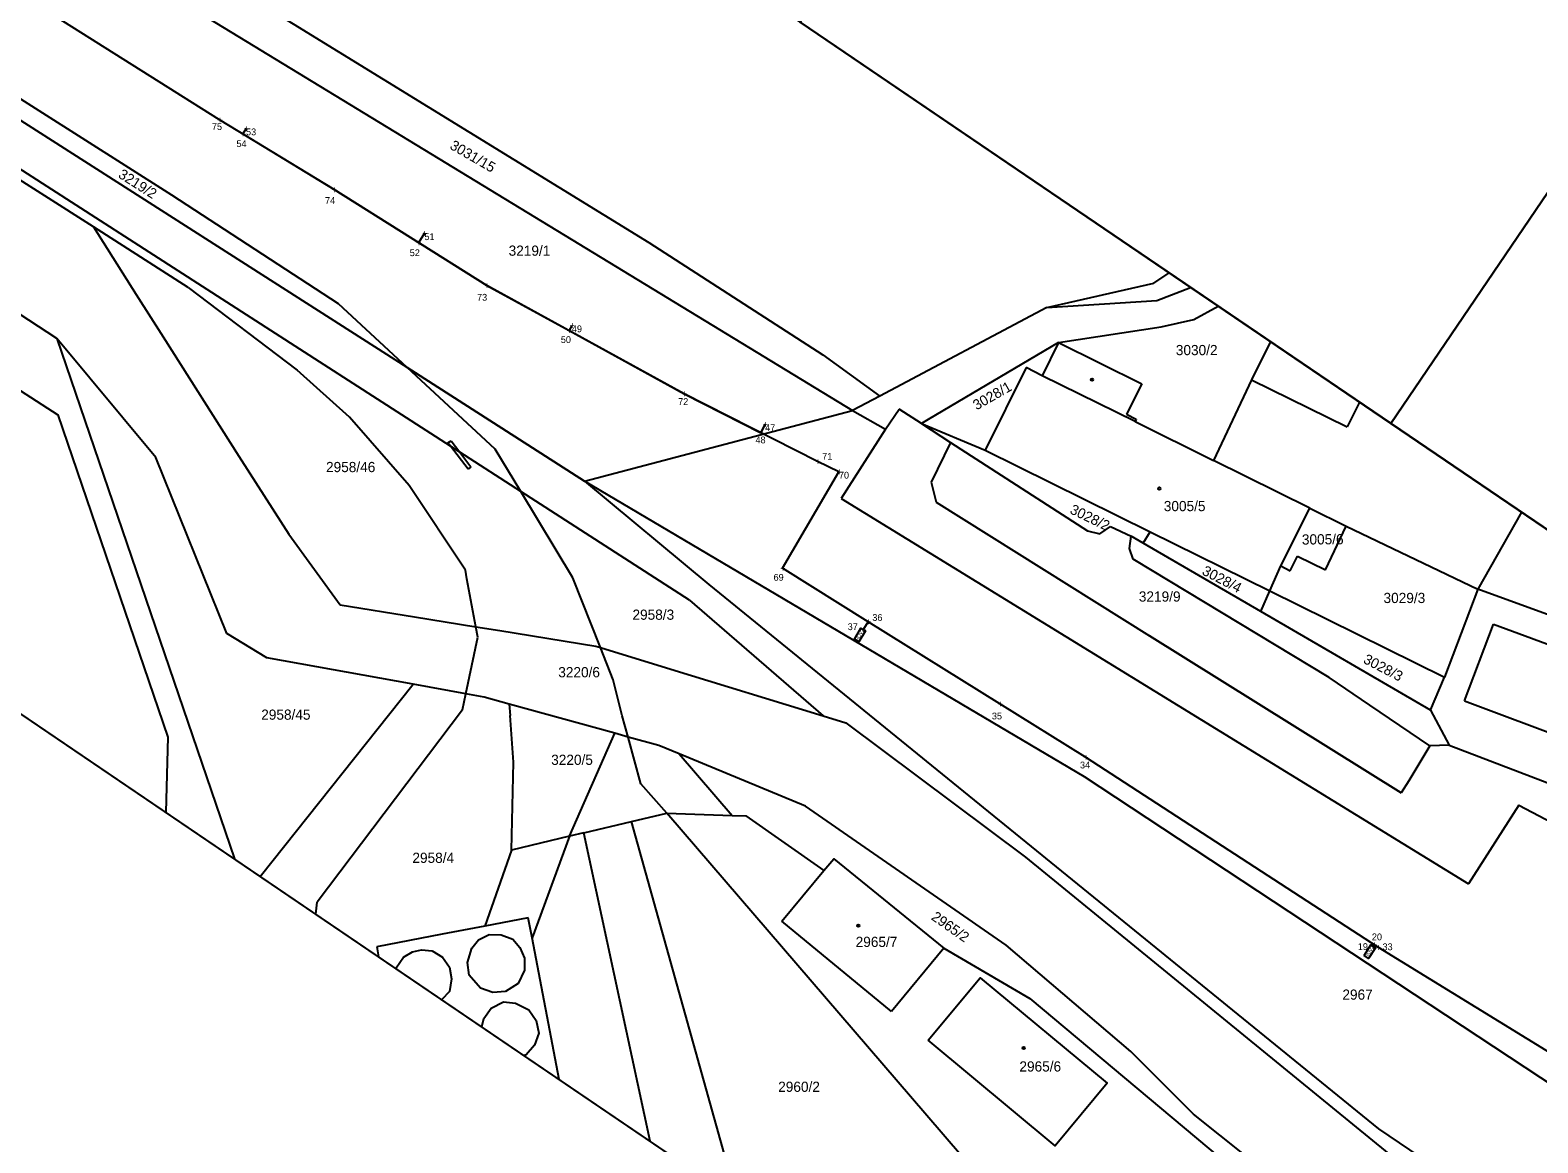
# Model space of a CAD drawing. Extents: x -621058 to -620023, y -1122866 to -1122030.
# Drawn here: x -620566.7 to -620345, y -1122671.6 to -1122508 of the extents above; entities that cross this region are included whole.
import ezdxf

# ---------------------------------------------------------------- set-up
doc = ezdxf.new("R2010")
doc.units = 0
for name, color, linetype in [('060604_ROZVODY_SEE', 7, 'Continuous'), ('BODY', 7, 'Continuous'), ('BODY POPIS', 7, 'Continuous'), ('RÁMY', 7, 'Continuous'), ('UZEMNĚNÍ', 7, 'Continuous'), ('Vrstva 53', 7, 'Continuous'), ('Vrstva 55', 7, 'Continuous'), ('Vrstva 56', 7, 'Continuous'), ('Vrstva 57', 7, 'Continuous')]:
    doc.layers.add(name, color=color, linetype=linetype)

msp = doc.modelspace()

# ---------------------------------------------------------------- linework, layer by layer
at = {"layer": '060604_ROZVODY_SEE'}
for p, q in [((-620535, -1122522.48), (-620535.49, -1122523.28)), ((-620508.77, -1122537.89), (-620509.64, -1122539.27)), ((-620487.09, -1122551.44), (-620487.51, -1122552.2)), ((-620458.67, -1122565.97), (-620459.3, -1122567.21)), ((-620369.27, -1122642.75), (-620369.11, -1122642.5))]:
    msp.add_line(p, q, dxfattribs=at)
for points in [[(-620443.53, -1122595), (-620456.11, -1122587.12), (-620447.82, -1122572.96), (-620450.95, -1122571.45), (-620470.59, -1122561.48), (-620499.61, -1122545.57), (-620522.04, -1122531.47), (-620538.89, -1122521.21), (-620599.21, -1122483.22), (-620683.52, -1122429.44), (-620756.33, -1122383.52), (-620765.8, -1122398.39)], [(-620243.03, -1122716), (-620248.32, -1122722.77), (-620259.89, -1122713.57), (-620277.71, -1122700.9), (-620282.35, -1122705.3), (-620297.82, -1122689.49), (-620304.22, -1122684.86), (-620310.82, -1122680.06), (-620316.82, -1122675.99), (-620322.23, -1122672.32), (-620326.63, -1122669.41), (-620343.18, -1122658.46), (-620368.5, -1122642.9), (-620411.56, -1122614.92), (-620424.16, -1122607.09), (-620443.53, -1122595), (-620444.24, -1122596.15)]]:
    msp.add_lwpolyline(points, dxfattribs=at)
for points in [[(-620445.54, -1122597.56), (-620444.58, -1122595.95), (-620443.91, -1122596.35), (-620444.87, -1122597.96)], [(-620370.61, -1122644.11), (-620369.6, -1122642.54), (-620368.94, -1122642.96), (-620369.95, -1122644.54)]]:
    msp.add_lwpolyline(points, close=True, dxfattribs=at)
at = {"layer": 'RÁMY'}
for points in [[(-620974.7, -1122152.91), (-620106.07, -1122742.82), (-620189.51, -1122865.67), (-621058.13, -1122275.76)], [(-620887.83, -1122211.9), (-620106.07, -1122742.82), (-620189.51, -1122865.67), (-620971.26, -1122334.75)], [(-620370.09, -1122384.01), (-620283.23, -1122443), (-620366.66, -1122565.85), (-620453.52, -1122506.86)], [(-620283.23, -1122443), (-620196.37, -1122501.99), (-620279.8, -1122624.84), (-620366.66, -1122565.85)]]:
    msp.add_lwpolyline(points, close=True, dxfattribs=at)
at = {"layer": 'UZEMNĚNÍ'}
msp.add_lwpolyline([(-620535, -1122522.48), (-620535.49, -1122523.28), (-620522.04, -1122531.47), (-620499.61, -1122545.57), (-620487.51, -1122552.2), (-620470.59, -1122561.48), (-620459.3, -1122567.21), (-620458.67, -1122565.97)], dxfattribs=at)
at = {"layer": 'Vrstva 53'}
for p, q in [((-620545.92, -1122532.26), (-620679.51, -1122447.56)), ((-620552.09, -1122499.2), (-620445.8, -1122563.95)), ((-620521.41, -1122548.27), (-620545.92, -1122532.26)), ((-620511.29, -1122557.64), (-620521.41, -1122548.27)), ((-620485.21, -1122574.33), (-620511.29, -1122557.64)), ((-620445.8, -1122563.95), (-620440.98, -1122566.69)), ((-620440.98, -1122566.69), (-620438.97, -1122563.76)), ((-620435.69, -1122565.88), (-620438.97, -1122563.76)), ((-620440.98, -1122566.69), (-620447.48, -1122576.88)), ((-620435.69, -1122565.88), (-620431.39, -1122568.66)), ((-620431.39, -1122568.66), (-620434.26, -1122574.5)), ((-620411.71, -1122617.81), (-620485.21, -1122574.33)), ((-620434.26, -1122574.5), (-620433.53, -1122577.42)), ((-620447.48, -1122576.88), (-620355.23, -1122633.54)), ((-620433.53, -1122577.42), (-620402.13, -1122597.06)), ((-620402.13, -1122597.06), (-620365.14, -1122620.19)), ((-620358.11, -1122613.18), (-620360.91, -1122613.28)), ((-620358.11, -1122613.18), (-620335.54, -1122621.75)), ((-620361.94, -1122614.97), (-620364.03, -1122618.38)), ((-620334.71, -1122668.63), (-620411.71, -1122617.81)), ((-620364.03, -1122618.38), (-620365.14, -1122620.19)), ((-620347.83, -1122621.96), (-620355.23, -1122633.54)), ((-620347.83, -1122621.96), (-620296.23, -1122649.3))]:
    msp.add_line(p, q, dxfattribs=at)
at = {"layer": 'Vrstva 55'}
for p, q in [((-620545.92, -1122532.26), (-620679.51, -1122447.56)), ((-620557.45, -1122536.96), (-620684.91, -1122455.63)), ((-620548.9, -1122494.24), (-620475.79, -1122539.24)), ((-620552.09, -1122499.2), (-620445.8, -1122563.95)), ((-620511.29, -1122557.64), (-620587.17, -1122509.18)), ((-620521.41, -1122548.27), (-620545.92, -1122532.26)), ((-620557.45, -1122536.96), (-620551.15, -1122546.87)), ((-620543.5, -1122545.86), (-620557.45, -1122536.96)), ((-620475.79, -1122539.24), (-620450.17, -1122555.76)), ((-620417.25, -1122548.82), (-620401.53, -1122545.24)), ((-620401.53, -1122545.24), (-620399.25, -1122543.72)), ((-620551.15, -1122546.87), (-620547.19, -1122553.1)), ((-620543.5, -1122545.86), (-620527.5, -1122558.02)), ((-620511.29, -1122557.64), (-620521.41, -1122548.27)), ((-620417.25, -1122548.82), (-620441.78, -1122561.82)), ((-620548.28, -1122570.88), (-620562.8, -1122553.35)), ((-620562.8, -1122553.35), (-620536.71, -1122629.87)), ((-620547.19, -1122553.1), (-620536.04, -1122570.64)), ((-620415.52, -1122553.94), (-620434.68, -1122565.28)), ((-620415.52, -1122553.94), (-620417.91, -1122558.83)), ((-620415.52, -1122553.94), (-620403.26, -1122560.03)), ((-620384.37, -1122553.82), (-620387.17, -1122559.43)), ((-620450.17, -1122555.76), (-620441.78, -1122561.82)), ((-620519.77, -1122564.93), (-620527.5, -1122558.02)), ((-620498.35, -1122569.65), (-620511.29, -1122557.64)), ((-620511.29, -1122557.64), (-620485.21, -1122574.33)), ((-620420.27, -1122557.63), (-620426.32, -1122569.77)), ((-620417.91, -1122558.83), (-620420.27, -1122557.63)), ((-620403.26, -1122560.03), (-620405.52, -1122564.49)), ((-620387.17, -1122559.43), (-620392.72, -1122571.3)), ((-620387.17, -1122559.43), (-620373.07, -1122566.34)), ((-620441.78, -1122561.82), (-620445.8, -1122563.95)), ((-620371.29, -1122562.71), (-620373.07, -1122566.34)), ((-620511.02, -1122574.99), (-620519.77, -1122564.93)), ((-620445.8, -1122563.95), (-620440.98, -1122566.69)), ((-620440.98, -1122566.69), (-620438.97, -1122563.76)), ((-620435.69, -1122565.88), (-620438.97, -1122563.76)), ((-620434.68, -1122565.28), (-620435.69, -1122565.88)), ((-620405.52, -1122564.49), (-620404.12, -1122565.22)), ((-620404.12, -1122565.22), (-620404.28, -1122565.56)), ((-620440.98, -1122566.69), (-620447.48, -1122576.88)), ((-620435.69, -1122565.88), (-620426.32, -1122569.77)), ((-620435.69, -1122565.88), (-620431.39, -1122568.66)), ((-620404.28, -1122565.56), (-620392.72, -1122571.3)), ((-620494.61, -1122575.85), (-620498.35, -1122569.65)), ((-620431.39, -1122568.66), (-620434.26, -1122574.5)), ((-620431.39, -1122568.66), (-620411.27, -1122581.65)), ((-620426.32, -1122569.77), (-620402.04, -1122581.77)), ((-620537.83, -1122596.73), (-620548.28, -1122570.88)), ((-620536.04, -1122570.64), (-620528.72, -1122582.15)), ((-620378.57, -1122578.31), (-620392.72, -1122571.3)), ((-620502.74, -1122587.44), (-620511.02, -1122574.99)), ((-620486.95, -1122588.56), (-620494.61, -1122575.85)), ((-620469.8, -1122591.86), (-620494.61, -1122575.85)), ((-620485.21, -1122574.33), (-620466.94, -1122589.51)), ((-620411.71, -1122617.81), (-620485.21, -1122574.33)), ((-620434.26, -1122574.5), (-620433.53, -1122577.42)), ((-620447.48, -1122576.88), (-620355.23, -1122633.54)), ((-620433.53, -1122577.42), (-620402.13, -1122597.06)), ((-620382.82, -1122586.79), (-620378.57, -1122578.31)), ((-620378.57, -1122578.31), (-620373.23, -1122580.96)), ((-620347.47, -1122578.88), (-620353.86, -1122590.22)), ((-620528.72, -1122582.15), (-620521.17, -1122592.53)), ((-620411.27, -1122581.65), (-620409.46, -1122582.07)), ((-620409.46, -1122582.07), (-620407.91, -1122580.98)), ((-620407.91, -1122580.98), (-620404.87, -1122582.42)), ((-620403.1, -1122583.45), (-620404.87, -1122582.42)), ((-620403.1, -1122583.45), (-620402.04, -1122581.77)), ((-620402.04, -1122581.77), (-620384.45, -1122590.46)), ((-620376.29, -1122587.36), (-620373.23, -1122580.96)), ((-620373.23, -1122580.96), (-620353.86, -1122590.22)), ((-620385.78, -1122593.52), (-620403.1, -1122583.45)), ((-620502.51, -1122588.68), (-620502.74, -1122587.44)), ((-620384.45, -1122590.46), (-620382.82, -1122586.79)), ((-620382.82, -1122586.79), (-620381.45, -1122587.52)), ((-620381.45, -1122587.52), (-620380.38, -1122585.36)), ((-620380.38, -1122585.36), (-620376.29, -1122587.36)), ((-620501.2, -1122595.75), (-620502.51, -1122588.68)), ((-620482.88, -1122598.82), (-620486.95, -1122588.56)), ((-620466.94, -1122589.51), (-620368.46, -1122669.58)), ((-620469.8, -1122591.86), (-620450.13, -1122608.86)), ((-620385.78, -1122593.52), (-620384.45, -1122590.46)), ((-620384.45, -1122590.46), (-620358.78, -1122603.15)), ((-620353.86, -1122590.22), (-620358.78, -1122603.15)), ((-620329.18, -1122599.21), (-620353.86, -1122590.22)), ((-620521.17, -1122592.53), (-620510.22, -1122594.3)), ((-620360.83, -1122608.03), (-620385.78, -1122593.52)), ((-620510.22, -1122594.3), (-620501.2, -1122595.75)), ((-620501.2, -1122595.75), (-620497.68, -1122596.32)), ((-620500.92, -1122597.26), (-620501.2, -1122595.75)), ((-620497.68, -1122596.32), (-620483.58, -1122598.6)), ((-620355.84, -1122606.66), (-620351.59, -1122595.35)), ((-620351.59, -1122595.35), (-620331.64, -1122602.77)), ((-620531.96, -1122600.32), (-620537.83, -1122596.73)), ((-620502.69, -1122605.61), (-620500.92, -1122597.26)), ((-620365.14, -1122620.19), (-620402.13, -1122597.06)), ((-620510.44, -1122604.21), (-620531.96, -1122600.32)), ((-620483.58, -1122598.6), (-620482.88, -1122598.82)), ((-620482.88, -1122598.82), (-620472.56, -1122601.98)), ((-620481, -1122603.54), (-620482.88, -1122598.82)), ((-620472.56, -1122601.98), (-620450.13, -1122608.86)), ((-620532.9, -1122632.46), (-620510.44, -1122604.21)), ((-620502.69, -1122605.61), (-620510.44, -1122604.21)), ((-620479.67, -1122608.86), (-620481, -1122603.54)), ((-620360.83, -1122608.03), (-620358.78, -1122603.15)), ((-620503.19, -1122607.95), (-620502.69, -1122605.61)), ((-620500, -1122606.09), (-620502.69, -1122605.61)), ((-620496.31, -1122607.11), (-620500, -1122606.09)), ((-620496.31, -1122607.11), (-620496.18, -1122608.79)), ((-620480.79, -1122611.41), (-620496.31, -1122607.11)), ((-620355.84, -1122606.66), (-620335.8, -1122614.14)), ((-620503.19, -1122607.95), (-620524.52, -1122636.25)), ((-620495.65, -1122615.65), (-620496.18, -1122608.79)), ((-620478.83, -1122611.96), (-620479.67, -1122608.86)), ((-620450.13, -1122608.86), (-620446.79, -1122609.88)), ((-620360.83, -1122608.03), (-620358.11, -1122613.18)), ((-620478.83, -1122611.96), (-620480.79, -1122611.41)), ((-620446.79, -1122609.88), (-620420.38, -1122629.64)), ((-620474.31, -1122613.21), (-620478.83, -1122611.96)), ((-620476.96, -1122618.82), (-620478.83, -1122611.96)), ((-620471.33, -1122614.44), (-620474.31, -1122613.21)), ((-620360.91, -1122613.28), (-620361.94, -1122614.97)), ((-620358.11, -1122613.18), (-620360.91, -1122613.28)), ((-620358.11, -1122613.18), (-620335.54, -1122621.75)), ((-620495.96, -1122628.58), (-620495.65, -1122615.65)), ((-620452.73, -1122622.13), (-620471.33, -1122614.44)), ((-620361.94, -1122614.97), (-620364.03, -1122618.38)), ((-620334.71, -1122668.63), (-620411.71, -1122617.81)), ((-620364.03, -1122618.38), (-620365.14, -1122620.19)), ((-620473.14, -1122623.15), (-620476.96, -1122618.82)), ((-620423.22, -1122642.55), (-620452.73, -1122622.13)), ((-620347.83, -1122621.96), (-620355.23, -1122633.54)), ((-620347.83, -1122621.96), (-620296.23, -1122649.3)), ((-620485.31, -1122626.04), (-620478.32, -1122624.38)), ((-620478.32, -1122624.38), (-620473.14, -1122623.15)), ((-620463.28, -1122678.3), (-620478.32, -1122624.38)), ((-620434.88, -1122667.63), (-620473.14, -1122623.15)), ((-620473.14, -1122623.15), (-620463.51, -1122623.5)), ((-620487.46, -1122626.56), (-620495.96, -1122628.58)), ((-620485.31, -1122626.04), (-620487.46, -1122626.56)), ((-620475.57, -1122671.39), (-620485.31, -1122626.04)), ((-620456.23, -1122639.05), (-620450.04, -1122631.61)), ((-620420.38, -1122629.64), (-620366.98, -1122673.23)), ((-620524.73, -1122638.01), (-620524.52, -1122636.25)), ((-620499.9, -1122639.77), (-620506.17, -1122640.97)), ((-620493.5, -1122638.55), (-620499.9, -1122639.77)), ((-620492.94, -1122641.47), (-620493.5, -1122638.55)), ((-620440.08, -1122652.3), (-620456.23, -1122639.05)), ((-620506.17, -1122640.97), (-620515.78, -1122642.8)), ((-620515.78, -1122642.8), (-620515.5, -1122644.28)), ((-620488.95, -1122662.31), (-620492.94, -1122641.47)), ((-620404.9, -1122658.18), (-620423.22, -1122642.55)), ((-620432.38, -1122643.03), (-620440.08, -1122652.3)), ((-620395.68, -1122667.41), (-620404.9, -1122658.18)), ((-620391.77, -1122717.74), (-620434.88, -1122667.63)), ((-620365.35, -1122691.52), (-620395.68, -1122667.41)), ((-620368.46, -1122669.58), (-620310.57, -1122708.76))]:
    msp.add_line(p, q, dxfattribs=at)
for points in [[(-620562.8, -1122553.35), (-620572.54, -1122547.06), (-620576.58, -1122544.45)], [(-620581.67, -1122552.32), (-620562.67, -1122564.59), (-620546.5, -1122612), (-620546.78, -1122623.03)], [(-620463.51, -1122623.5), (-620461.53, -1122623.57), (-620450.04, -1122631.61)], [(-620450.04, -1122631.61), (-620448.58, -1122629.86), (-620432.38, -1122643.03)], [(-620432.38, -1122643.03), (-620419.73, -1122650.41), (-620372.55, -1122689.97), (-620363.06, -1122698.75), (-620352.08, -1122712.18), (-620349.5, -1122720.4)], [(-620434.7, -1122656.53), (-620427.07, -1122647.39), (-620408.37, -1122662.86), (-620416.01, -1122672.06), (-620434.7, -1122656.53)]]:
    msp.add_lwpolyline(points, dxfattribs=at)
at = {"layer": 'Vrstva 56'}
for p, q in [((-620504.94, -1122569.2), (-620570.69, -1122526.84)), ((-620401.09, -1122547.76), (-620396.12, -1122545.84)), ((-620417.25, -1122548.82), (-620401.09, -1122547.76)), ((-620395.61, -1122550.55), (-620392.04, -1122548.61)), ((-620415.52, -1122553.94), (-620400.46, -1122551.66)), ((-620400.46, -1122551.66), (-620395.61, -1122550.55)), ((-620404.28, -1122565.56), (-620417.91, -1122558.83)), ((-620485.21, -1122574.33), (-620445.8, -1122563.95)), ((-620505.32, -1122568.68), (-620504.84, -1122568.4)), ((-620504.94, -1122569.2), (-620505.32, -1122568.68)), ((-620503.56, -1122570.07), (-620504.94, -1122569.2)), ((-620502.33, -1122572.56), (-620504.94, -1122569.2)), ((-620504.84, -1122568.4), (-620503.56, -1122570.07)), ((-620494.61, -1122575.85), (-620503.56, -1122570.07)), ((-620503.56, -1122570.07), (-620501.96, -1122572.22)), ((-620501.96, -1122572.22), (-620502.33, -1122572.56)), ((-620405.1, -1122584.22), (-620404.87, -1122582.42)), ((-620404.53, -1122585.79), (-620405.1, -1122584.22)), ((-620375.73, -1122603.21), (-620404.53, -1122585.79)), ((-620369.73, -1122607.28), (-620375.73, -1122603.21)), ((-620360.91, -1122613.28), (-620369.73, -1122607.28)), ((-620487.46, -1122626.56), (-620480.79, -1122611.41)), ((-620471.33, -1122614.44), (-620463.51, -1122623.5)), ((-620487.46, -1122626.56), (-620492.94, -1122641.47)), ((-620495.96, -1122628.58), (-620499.9, -1122639.77)), ((-620501.82, -1122643), (-620500.81, -1122641.76)), ((-620500.81, -1122641.76), (-620499.26, -1122640.98)), ((-620499.26, -1122640.98), (-620497.47, -1122641.06)), ((-620497.47, -1122641.06), (-620495.76, -1122641.68)), ((-620495.76, -1122641.68), (-620494.75, -1122642.92)), ((-620494.75, -1122642.92), (-620494.06, -1122644.48)), ((-620512.93, -1122645.88), (-620511.84, -1122644.32)), ((-620511.84, -1122644.32), (-620510.52, -1122643.55)), ((-620510.52, -1122643.55), (-620509.2, -1122643.23)), ((-620509.2, -1122643.23), (-620507.65, -1122643.39)), ((-620507.65, -1122643.39), (-620506.09, -1122644.32)), ((-620506.09, -1122644.32), (-620505.08, -1122645.8)), ((-620502.44, -1122645.1), (-620501.82, -1122643)), ((-620502.21, -1122646.96), (-620502.44, -1122645.1)), ((-620494.06, -1122644.48), (-620494.06, -1122646.26)), ((-620512.93, -1122646.02), (-620512.93, -1122645.88)), ((-620505.08, -1122645.8), (-620504.77, -1122647.51)), ((-620500.5, -1122648.9), (-620502.21, -1122646.96)), ((-620494.06, -1122646.26), (-620494.99, -1122648.21)), ((-620505.08, -1122649.37), (-620506.22, -1122650.58)), ((-620504.77, -1122647.51), (-620505.08, -1122649.37)), ((-620498.71, -1122649.52), (-620500.5, -1122648.9)), ((-620496.85, -1122649.37), (-620498.71, -1122649.52)), ((-620494.99, -1122648.21), (-620496.85, -1122649.37)), ((-620498.95, -1122651.85), (-620497.16, -1122650.92)), ((-620497.16, -1122650.92), (-620495.38, -1122651.08)), ((-620495.38, -1122651.08), (-620493.43, -1122652.09)), ((-620500.34, -1122654.57), (-620500.03, -1122653.33)), ((-620500.03, -1122653.33), (-620498.95, -1122651.85)), ((-620493.43, -1122652.09), (-620492.35, -1122653.64)), ((-620492.35, -1122653.64), (-620491.96, -1122655.5)), ((-620491.96, -1122655.5), (-620492.58, -1122657.29)), ((-620492.58, -1122657.29), (-620493.82, -1122658.69)), ((-620493.82, -1122658.69), (-620494.1, -1122658.81))]:
    msp.add_line(p, q, dxfattribs=at)
at = {"layer": 'Vrstva 57'}
for centre in [(-620410.59, -1122559.41), (-620400.71, -1122575.42), (-620444.98, -1122639.7), (-620420.65, -1122657.67)]:
    msp.add_circle(centre, 0.175, dxfattribs=at)

# ---------------------------------------------------------------- texts
at = {"layer": '060604_ROZVODY_SEE'}
for s, rotation, p in [('ROV3', 59.2059, (-620445.04, -1122597.88)), ('ROV2', 57.376, (-620370.12, -1122644.44))]:
    msp.add_text(s, height=0.5, rotation=rotation, dxfattribs=at).set_placement(p)
at = {"layer": 'BODY'}
for p in [(-620539.22, -1122521.71), (-620535.82, -1122523.78), (-620535.33, -1122522.98), (-620522.37, -1122531.97), (-620509.11, -1122538.39), (-620509.97, -1122539.77), (-620499.94, -1122546.07), (-620487.85, -1122552.7), (-620487.43, -1122551.94), (-620470.93, -1122561.98), (-620459.63, -1122567.71), (-620459, -1122566.47), (-620451.28, -1122571.95), (-620448.16, -1122573.46), (-620456.44, -1122587.62), (-620444.58, -1122596.65), (-620443.86, -1122595.5), (-620424.49, -1122607.59), (-620411.89, -1122615.42), (-620369.61, -1122643.25), (-620369.45, -1122643), (-620368.83, -1122643.4)]:
    msp.add_text('+', height=1, dxfattribs=at).set_placement(p)
at = {"layer": 'BODY POPIS'}
for s, p in [('75', (-620540.02, -1122522.7)), ('53', (-620535, -1122523.48)), ('54', (-620536.41, -1122525.21)), ('74', (-620523.39, -1122533.57)), ('51', (-620508.77, -1122538.89)), ('52', (-620510.93, -1122541.25)), ('73', (-620501.03, -1122547.8)), ('49', (-620487.09, -1122552.44)), ('50', (-620488.71, -1122554.02)), ('72', (-620471.46, -1122563.13)), ('47', (-620458.67, -1122566.97)), ('48', (-620460.09, -1122568.78)), ('71', (-620450.28, -1122571.19)), ('70', (-620447.82, -1122573.96)), ('69', (-620457.43, -1122588.98)), ('36', (-620442.91, -1122594.89)), ('37', (-620446.53, -1122596.24)), ('35', (-620425.33, -1122609.37)), ('34', (-620412.37, -1122616.58)), ('19', (-620371.52, -1122643.28)), ('20', (-620369.45, -1122641.85)), ('33', (-620367.89, -1122643.31))]:
    msp.add_text(s, height=1, dxfattribs=at).set_placement(p)
at = {"layer": 'Vrstva 57'}
for s, rotation, p in [('3031/15', 330.0385, (-620505.16, -1122525.39)), ('3219/2', 327.6, (-620553.91, -1122529.6)), ('3028/1', 29.7, (-620427.58, -1122563.94)), ('3028/2', 334.1384, (-620413.98, -1122579.01)), ('3005/6', 0.4373, (-620379.74, -1122583.66)), ('3028/4', 332.452, (-620394.55, -1122587.99)), ('3028/3', 332.5324, (-620370.84, -1122601)), ('2965/2', 325.0126, (-620434.36, -1122638.71))]:
    msp.add_text(s, height=1.5, rotation=rotation, dxfattribs=at).set_placement(p)
for s, p in [('3219/1', (-620496.39, -1122541.19)), ('3030/2', (-620398.28, -1122555.81)), ('2958/46', (-620523.24, -1122573.01)), ('3005/5', (-620400.05, -1122578.75)), ('3219/9', (-620403.72, -1122592.05)), ('3029/3', (-620367.74, -1122592.26)), ('2958/3', (-620478.18, -1122594.72)), ('3220/6', (-620489.09, -1122603.18)), ('2958/45', (-620532.77, -1122609.42)), ('3220/5', (-620490.13, -1122616.06)), ('2958/4', (-620510.54, -1122630.47)), ('2965/7', (-620445.36, -1122642.83)), ('2967', (-620373.79, -1122650.59)), ('2965/6', (-620421.28, -1122661.15)), ('2960/2', (-620456.75, -1122664.14))]:
    msp.add_text(s, height=1.5, dxfattribs=at).set_placement(p)

doc.saveas('drawing.dxf')
